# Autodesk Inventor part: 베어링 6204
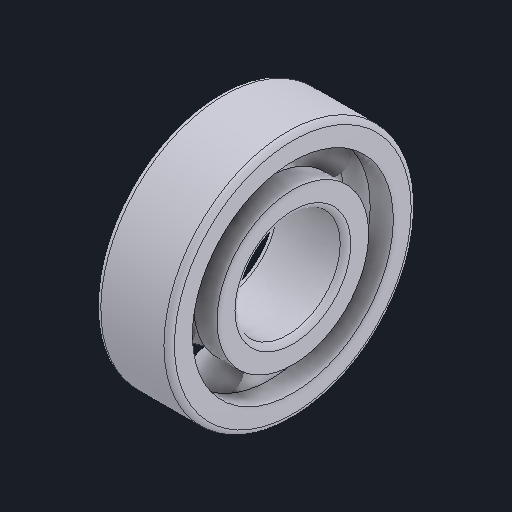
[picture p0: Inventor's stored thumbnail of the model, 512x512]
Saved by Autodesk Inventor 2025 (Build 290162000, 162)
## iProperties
Created: 2025-08
Part Number: 베어링 6204
Material: 강철, 연강
Description: 깊은 그루브 볼 베어링
Document SubType Name: Modeling
Designer: infra17
Density: 7.86 g/cm^3
Appearance: 기본값
Author: jhkim
Sending System: Autodesk Inventor 2026
Preprocessor: ST-DEVELOPER v20.1
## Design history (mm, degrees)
feature "Solid1"
feature "Solid1:1"
feature "Solid1:2"
feature "Solid1:3"
feature "Solid1:4"
feature "Solid1:5"
feature "Solid1:6"
feature "Solid1:7"
feature "Solid1:8"
node "솔리드1"
node "솔리드2"
node "솔리드3"
node "솔리드4"
node "솔리드5"
node "솔리드6"
node "솔리드7"
node "솔리드8"
node "솔리드9"
